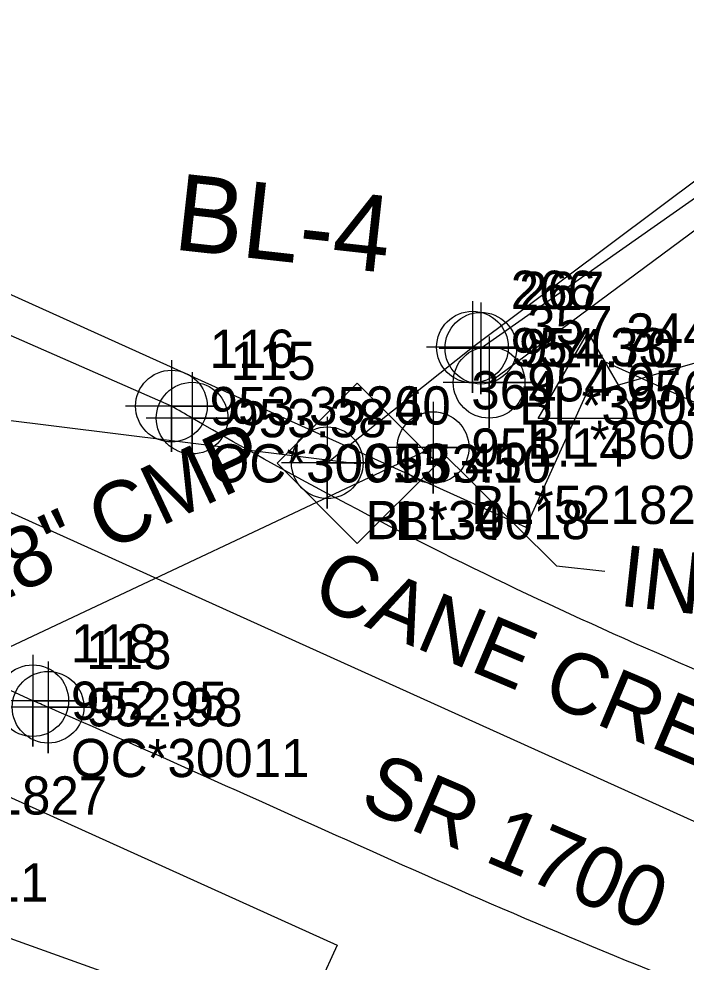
# Model space of a CAD drawing. Extents: x 1150279 to 1151282, y 654632 to 657999.
# Drawn here: x 1150909.2 to 1150952.8, y 657073.4 to 657135.2 of the extents above; entities that cross this region are included whole.
import ezdxf

# ---------------------------------------------------------------- set-up
doc = ezdxf.new("R2010")
doc.units = 0
for name, color, linetype in [('COGO Default Chain', 7, 'Continuous'), ('CTL Supplemental Horizontal and Vertical CELL', 7, 'Continuous'), ('CTL Supplemental Horizontal and Vertical Cogo Comment', 7, 'Continuous'), ('CTL Supplemental Horizontal and Vertical Cogo Elevation', 7, 'Continuous'), ('CTL Supplemental Horizontal and Vertical Cogo Number', 7, 'Continuous'), ('CTL Supplemental Horizontal and Vertical Text', 7, 'Continuous'), ('Exist Horizontal Alignment', 7, 'Continuous'), ('Exist Other Culture Fence Line', 7, 'Continuous'), ('Exist Other Culture Fence Line Cogo Elevation', 7, 'Continuous'), ('Exist Right of Way Line', 7, 'Continuous'), ('Exist Right of Way Monument CELL', 7, 'Continuous'), ('Exist Right of Way Monument Cogo Elevation', 7, 'Continuous'), ('Exist Right of Way Monument Cogo Number', 7, 'Continuous'), ('Exist Right of Way Monument Leader', 7, 'Continuous'), ('Exist Roads Curbs', 7, 'Continuous'), ('Exist Roads Curbs Cogo Comment', 7, 'Continuous'), ('Exist Roads Curbs Cogo Elevation', 7, 'Continuous'), ('Exist Roads Curbs Cogo Number', 7, 'Continuous'), ('Exist Roads Curbs Cogo Point CELL', 7, 'Continuous'), ('Exist Roads EOP', 7, 'Continuous'), ('Exist Roads EOP Cogo Comment', 7, 'Continuous'), ('Exist Roads EOP Cogo Elevation', 7, 'Continuous'), ('Exist Roads EOP Cogo Number', 7, 'Continuous'), ('Exist Roads EOP Cogo Point CELL', 7, 'Continuous'), ('Exist Roads EOP Text', 7, 'Continuous'), ('Exist Structure Minor Pipes CMP 15 Inch Leader', 7, 'Continuous'), ('Exist Structure Minor Pipes CMP 15 Inch Text', 7, 'Continuous'), ('Exist Structure Minor Pipes CMP 18 Inch', 7, 'Continuous'), ('Exist Structure Minor Pipes CMP 18 Inch Cogo Comment', 7, 'Continuous'), ('Exist Structure Minor Pipes CMP 18 Inch Cogo Elevation', 7, 'Continuous'), ('Exist Structure Minor Pipes CMP 18 Inch Cogo Number', 7, 'Continuous'), ('Exist Structure Minor Pipes CMP 18 Inch Cogo Point CELL', 7, 'Continuous'), ('Exist Structure Minor Pipes CMP 18 Inch Text', 7, 'Continuous'), ('Exist Vegetation Hedge Row', 7, 'Continuous'), ('Exist Vegetation Hedge Row Cogo Comment', 7, 'Continuous'), ('Exist Vegetation Hedge Row Cogo Elevation', 7, 'Continuous'), ('Exist Vegetation Hedge Row Cogo Number', 7, 'Continuous'), ('Exist Vegetation Hedge Row Cogo Point CELL', 7, 'Continuous')]:
    doc.layers.add(name, color=color, linetype=linetype)

msp = doc.modelspace()

# ---------------------------------------------------------------- linework, layer by layer
at = {"layer": 'COGO Default Chain'}
for p, q in [((1150614.756, 657145.261), (1150931.292, 657106.062)), ((1150875.785, 657117.706), (1150962.476, 657078.528))]:
    msp.add_line(p, q, dxfattribs=at)
at = {"layer": 'CTL Supplemental Horizontal and Vertical CELL'}
msp.add_line((1150931.292, 657106.062), (1150931.292, 657106.062), dxfattribs=at)
msp.add_lwpolyline([(1150926.077, 657106.08), (1150931.318, 657111.321), (1150936.569, 657106.071), (1150931.327, 657100.83)], close=True, dxfattribs=at)
at = {"layer": 'Exist Horizontal Alignment'}
msp.add_line((1150875.785, 657117.706), (1150962.476, 657078.528), dxfattribs=at)
at = {"layer": 'Exist Other Culture Fence Line'}
msp.add_lwpolyline([(1151064.379, 657042.204), (1151035.792, 657039.664), (1150986.531, 657050.151), (1150941.416, 657063.204), (1150898.391, 657078.653), (1150854.858, 657094.995), (1150825.025, 657100.534), (1150812.457, 657091.594), (1150835.172, 657043.741), (1150852.719, 657007.431)], dxfattribs=at)
at = {"layer": 'Exist Right of Way Line'}
for p, q in [((1150881.139, 657129.553), (1150942.356, 657101.887)), ((1150947.298, 657112.822), (1150942.356, 657101.887)), ((1150947.298, 657112.822), (1150972.772, 657101.31)), ((1150868.784, 657102.215), (1150930.001, 657074.549)), ((1150930.001, 657074.549), (1150926.706, 657067.259))]:
    msp.add_line(p, q, dxfattribs=at)
at = {"layer": 'Exist Right of Way Monument CELL'}
msp.add_line((1150946.422, 657110.885), (1150946.422, 657110.885), dxfattribs=at)
msp.add_lwpolyline([(1150943.173, 657108.997), (1150946.423, 657114.635), (1150949.67, 657108.996)], close=True, dxfattribs=at)
at = {"layer": 'Exist Right of Way Monument Leader'}
msp.add_lwpolyline([(1150946.455, 657110.649), (1150955.645, 657113.292), (1150964.436, 657112.319)], dxfattribs=at)
at = {"layer": 'Exist Roads Curbs'}
msp.add_line((1150939.414, 657113.606), (1150959.746, 657127.905), dxfattribs=at)
at = {"layer": 'Exist Roads Curbs Cogo Point CELL'}
msp.add_lwpolyline([(1150939.414, 657116.606), (1150939.414, 657110.606), (1150939.414, 657113.606), (1150936.684, 657113.606), (1150942.414, 657113.606)], dxfattribs=at)
msp.add_circle((1150939.414, 657113.606), 2.344, dxfattribs=at)
at = {"layer": 'Exist Roads EOP'}
for p, q in [((1150919.164, 657109.821), (1150874.311, 657129.486)), ((1150910.091, 657090.545), (1150866.518, 657110.593))]:
    msp.add_line(p, q, dxfattribs=at)
msp.add_lwpolyline([(1150929.365, 657106.111), (1150938.865, 657113.677), (1150959.994, 657129.491)], dxfattribs=at)
for points in [[(1151056.232, 657077.091), (1151010.245, 657076.049), (1150965.316, 657087.792), (1150920.52, 657109.03), (1150919.164, 657109.821)], [(1151056.975, 657058.926), (1151008.048, 657058.299), (1150957.779, 657070.103), (1150911.093, 657090.114), (1150910.091, 657090.545)]]:
    msp.add_spline(points, degree=3, dxfattribs=at)
at = {"layer": 'Exist Roads EOP Cogo Point CELL'}
for points in [[(1150938.865, 657116.677), (1150938.865, 657110.677), (1150938.865, 657113.677), (1150941.865, 657113.677), (1150935.865, 657113.677)], [(1150919.164, 657112.821), (1150919.164, 657106.821), (1150919.164, 657109.821), (1150922.164, 657109.821), (1150916.164, 657109.821)], [(1150920.52, 657112.03), (1150920.52, 657106.03), (1150920.52, 657109.03), (1150923.52, 657109.03), (1150917.52, 657109.03)], [(1150929.365, 657109.111), (1150929.365, 657103.111), (1150929.365, 657106.111), (1150932.365, 657106.111), (1150926.365, 657106.111)], [(1150910.091, 657093.545), (1150910.091, 657087.545), (1150910.091, 657090.545), (1150913.091, 657090.545), (1150907.091, 657090.545)], [(1150911.093, 657093.114), (1150911.093, 657087.114), (1150911.093, 657090.114), (1150914.093, 657090.114), (1150908.093, 657090.114)]]:
    msp.add_lwpolyline(points, dxfattribs=at)
for centre in [(1150938.865, 657113.677), (1150919.164, 657109.821), (1150920.52, 657109.03), (1150929.365, 657106.111), (1150910.091, 657090.545), (1150911.093, 657090.114)]:
    msp.add_circle(centre, 2.344, dxfattribs=at)
at = {"layer": 'Exist Structure Minor Pipes CMP 15 Inch Leader'}
msp.add_lwpolyline([(1150936.514, 657107.147), (1150944.362, 657099.378), (1150947.527, 657099.028)], dxfattribs=at)
at = {"layer": 'Exist Structure Minor Pipes CMP 18 Inch'}
msp.add_line((1150936.288, 657107.106), (1150895.921, 657088.095), dxfattribs=at)
at = {"layer": 'Exist Structure Minor Pipes CMP 18 Inch Cogo Point CELL'}
msp.add_lwpolyline([(1150936.288, 657110.106), (1150936.288, 657104.106), (1150936.288, 657107.106), (1150939.288, 657107.106), (1150933.288, 657107.106)], dxfattribs=at)
msp.add_circle((1150936.288, 657107.106), 2.344, dxfattribs=at)
at = {"layer": 'Exist Vegetation Hedge Row'}
msp.add_line((1150939.948, 657111.372), (1150959.188, 657125.623), dxfattribs=at)
at = {"layer": 'Exist Vegetation Hedge Row Cogo Point CELL'}
msp.add_lwpolyline([(1150939.948, 657114.372), (1150939.948, 657108.372), (1150939.948, 657111.372), (1150942.948, 657111.372), (1150936.948, 657111.372)], dxfattribs=at)
msp.add_circle((1150939.948, 657111.372), 2.344, dxfattribs=at)

# ---------------------------------------------------------------- texts
at = {"layer": 'CTL Supplemental Horizontal and Vertical Cogo Comment'}
msp.add_text('BL-4', height=2.5, dxfattribs=at).set_placement((1150933.792, 657101.062))
at = {"layer": 'CTL Supplemental Horizontal and Vertical Cogo Elevation'}
msp.add_text('953.10', height=2.5, dxfattribs=at).set_placement((1150933.792, 657104.812))
at = {"layer": 'CTL Supplemental Horizontal and Vertical Cogo Number'}
msp.add_text('4', height=2.5, dxfattribs=at).set_placement((1150933.792, 657108.562))
at = {"layer": 'CTL Supplemental Horizontal and Vertical Text'}
msp.add_text('BL-4', height=5, rotation=353.6867, dxfattribs=at).set_placement((1150919.205, 657120.078))
at = {"layer": 'Exist Other Culture Fence Line Cogo Elevation'}
msp.add_text('950.11', height=2.5, dxfattribs=at).set_placement((1150900.891, 657077.403))
at = {"layer": 'Exist Right of Way Monument Cogo Elevation'}
msp.add_text('956.15', height=2.5, dxfattribs=at).set_placement((1150948.922, 657109.635))
at = {"layer": 'Exist Right of Way Monument Cogo Number'}
msp.add_text('344', height=2.5, dxfattribs=at).set_placement((1150948.922, 657113.385))
at = {"layer": 'Exist Roads Curbs Cogo Comment'}
msp.add_text('BL*30049', height=2.5, dxfattribs=at).set_placement((1150941.914, 657108.606))
at = {"layer": 'Exist Roads Curbs Cogo Elevation'}
msp.add_text('954.70', height=2.5, dxfattribs=at).set_placement((1150941.914, 657112.356))
at = {"layer": 'Exist Roads Curbs Cogo Number'}
msp.add_text('267', height=2.5, dxfattribs=at).set_placement((1150941.914, 657116.106))
at = {"layer": 'Exist Roads EOP Cogo Comment'}
for s, p in [('OC*30013', (1150921.664, 657104.821)), ('BL*30018', (1150931.865, 657101.111)), ('OC*30011', (1150912.591, 657085.545))]:
    msp.add_text(s, height=2.5, dxfattribs=at).set_placement(p)
at = {"layer": 'Exist Roads EOP Cogo Elevation'}
for s, p in [('954.33', (1150941.365, 657112.427)), ('953.35', (1150921.664, 657108.571)), ('953.38', (1150923.02, 657107.78)), ('953.45', (1150931.865, 657104.861)), ('952.95', (1150912.591, 657089.295)), ('952.98', (1150913.593, 657088.864))]:
    msp.add_text(s, height=2.5, dxfattribs=at).set_placement(p)
at = {"layer": 'Exist Roads EOP Cogo Number'}
for s, p in [('266', (1150941.365, 657116.177)), ('116', (1150921.664, 657112.321)), ('115', (1150923.02, 657111.53)), ('260', (1150931.865, 657108.611)), ('118', (1150912.591, 657093.045)), ('113', (1150913.593, 657092.614))]:
    msp.add_text(s, height=2.5, dxfattribs=at).set_placement(p)
at = {"layer": 'Exist Roads EOP Text'}
for s, rotation, p in [('CANE CREEK MTN. RD.', 337.10646, (1150928.179, 657096.94)), ('SR 1700', 336.80986, (1150931.345, 657083.599))]:
    msp.add_text(s, height=4, rotation=rotation, dxfattribs=at).set_placement(p)
at = {"layer": 'Exist Structure Minor Pipes CMP 15 Inch Text'}
msp.add_text("INV=951.14'", height=4, rotation=353.6867, dxfattribs=at).set_placement((1150948.372, 657096.768))
at = {"layer": 'Exist Structure Minor Pipes CMP 18 Inch Cogo Comment'}
for s, p in [('BL*521827', (1150938.788, 657102.106)), ('EL*521827', (1150898.421, 657083.095))]:
    msp.add_text(s, height=2.5, dxfattribs=at).set_placement(p)
at = {"layer": 'Exist Structure Minor Pipes CMP 18 Inch Cogo Elevation'}
msp.add_text('951.14', height=2.5, dxfattribs=at).set_placement((1150938.788, 657105.856))
at = {"layer": 'Exist Structure Minor Pipes CMP 18 Inch Cogo Number'}
msp.add_text('364', height=2.5, dxfattribs=at).set_placement((1150938.788, 657109.606))
at = {"layer": 'Exist Structure Minor Pipes CMP 18 Inch Text'}
msp.add_text('18" CMP', height=4, rotation=25.21932, dxfattribs=at).set_placement((1150906.519, 657096.292))
at = {"layer": 'Exist Vegetation Hedge Row Cogo Comment'}
msp.add_text('BL*360326', height=2.5, dxfattribs=at).set_placement((1150942.448, 657106.372))
at = {"layer": 'Exist Vegetation Hedge Row Cogo Elevation'}
msp.add_text('954.07', height=2.5, dxfattribs=at).set_placement((1150942.448, 657110.122))
at = {"layer": 'Exist Vegetation Hedge Row Cogo Number'}
msp.add_text('357', height=2.5, dxfattribs=at).set_placement((1150942.448, 657113.872))

doc.saveas('drawing.dxf')
